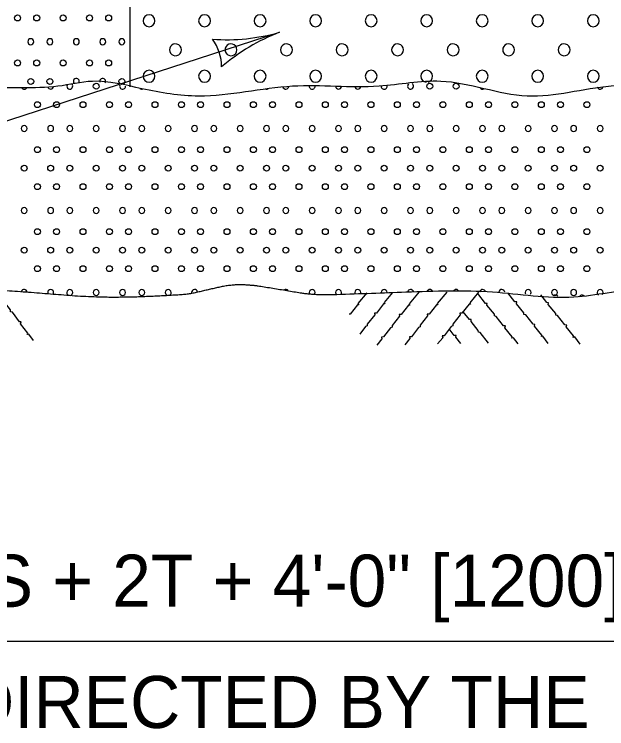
# Model space of a CAD drawing. Extents: x 49991.4 to 50021, y 49987.6 to 50011.4.
# Drawn here: x 50008.777 to 50009.461, y 49992.407 to 49993.231 of the extents above; entities that cross this region are included whole.
import ezdxf

# ---------------------------------------------------------------- set-up
doc = ezdxf.new("R2010")
doc.units = 0
for name, color, linetype in [('Level 1', 7, 'Continuous'), ('Level 2', 7, 'Continuous'), ('Level 3', 7, 'Continuous')]:
    doc.layers.add(name, color=color, linetype=linetype)

msp = doc.modelspace()

# ---------------------------------------------------------------- linework, layer by layer
at = {"layer": 'Level 1'}
msp.add_line((50008.91072, 49993.26941), (50008.91072, 49993.14749), dxfattribs=at)
for points in [[(50008.79939, 49992.85485), (50008.79419, 49992.86215), (50008.79239, 49992.86185), (50008.79279, 49992.86335), (50008.78469, 49992.87415), (50008.78529, 49992.87625), (50008.78319, 49992.87645), (50008.77509, 49992.88755), (50008.77309, 49992.88805), (50008.77289, 49992.89005), (50008.76479, 49992.90065), (50008.76519, 49992.90265), (50008.76309, 49992.90275), (50008.75679, 49992.91145)], [(50009.18429, 49992.90965), (50009.17409, 49992.89745), (50009.17499, 49992.89585), (50009.17339, 49992.89585), (50009.16499, 49992.88525), (50009.16389, 49992.88525)], [(50009.21399, 49992.91025), (50009.20439, 49992.89865), (50009.20519, 49992.89705), (50009.20359, 49992.89705), (50009.19529, 49992.88645), (50009.19309, 49992.88645), (50009.19339, 49992.88435), (50009.18479, 49992.87365), (50009.18479, 49992.87165), (50009.18289, 49992.87095), (50009.17609, 49992.86215)], [(50009.24469, 49992.91095), (50009.23309, 49992.89715), (50009.23389, 49992.89555), (50009.23229, 49992.89555), (50009.22399, 49992.88495), (50009.22179, 49992.88495), (50009.22209, 49992.88295), (50009.21349, 49992.87215), (50009.21349, 49992.87015), (50009.21169, 49992.86945), (50009.20349, 49992.85885), (50009.20139, 49992.85875), (50009.20179, 49992.85675), (50009.19589, 49992.84945)], [(50009.27649, 49992.91075), (50009.26539, 49992.89745), (50009.26619, 49992.89585), (50009.26459, 49992.89585), (50009.25619, 49992.88525), (50009.25409, 49992.88525), (50009.25439, 49992.88315), (50009.24569, 49992.87245), (50009.24569, 49992.87045), (50009.24389, 49992.86975), (50009.23569, 49992.85915), (50009.23369, 49992.85895), (50009.23409, 49992.85695), (50009.22809, 49992.84975)], [(50009.31329, 49992.91065), (50009.30309, 49992.89845), (50009.30389, 49992.89685), (50009.30229, 49992.89685), (50009.29399, 49992.88625), (50009.29179, 49992.88625), (50009.29209, 49992.88425), (50009.28349, 49992.87355), (50009.28349, 49992.87155), (50009.28169, 49992.87085), (50009.27349, 49992.86025), (50009.27139, 49992.86005), (50009.27189, 49992.85805), (50009.26589, 49992.85085)], [(50009.35899, 49992.85085), (50009.35359, 49992.85795), (50009.35179, 49992.85755), (50009.35219, 49992.85905), (50009.34379, 49992.86955), (50009.34419, 49992.87165), (50009.34219, 49992.87185), (50009.33369, 49992.88265), (50009.33169, 49992.88315), (50009.33149, 49992.88515), (50009.32299, 49992.89555), (50009.32329, 49992.89745), (50009.32129, 49992.89755), (50009.31249, 49992.90885)], [(50009.39379, 49992.85145), (50009.38749, 49992.85965), (50009.38579, 49992.85925), (50009.38619, 49992.86085), (50009.37769, 49992.87135), (50009.37819, 49992.87345), (50009.37619, 49992.87365), (50009.36769, 49992.88445), (50009.36569, 49992.88485), (50009.36549, 49992.88685), (50009.35699, 49992.89725), (50009.35729, 49992.89925), (50009.35519, 49992.89925), (50009.34699, 49992.90995)], [(50009.43059, 49992.85065), (50009.42439, 49992.85885), (50009.42259, 49992.85845), (50009.42299, 49992.86005), (50009.41459, 49992.87055), (50009.41509, 49992.87265), (50009.41299, 49992.87285), (50009.40449, 49992.88365), (50009.40259, 49992.88405), (50009.40229, 49992.88605), (50009.39379, 49992.89645), (50009.39419, 49992.89845), (50009.39209, 49992.89855), (50009.38499, 49992.90755)], [(50009.32489, 49992.85175), (50009.31519, 49992.86405), (50009.31329, 49992.86445), (50009.31299, 49992.86645), (50009.30459, 49992.87685), (50009.30489, 49992.87885), (50009.30279, 49992.87885), (50009.29569, 49992.88805)], [(50009.29299, 49992.85125), (50009.28699, 49992.85865), (50009.28729, 49992.86075), (50009.28519, 49992.86075), (50009.27939, 49992.86825)]]:
    msp.add_lwpolyline(points, dxfattribs=at)
for centre in [(50008.78109, 49993.22697), (50008.80323, 49993.22697), (50008.83371, 49993.22697), (50008.86419, 49993.22697), (50008.88633, 49993.22697), (50008.78109, 49993.17505), (50008.80323, 49993.17505), (50008.83371, 49993.17505), (50008.86419, 49993.17505), (50008.88633, 49993.17505), (50008.79633, 49993.15371), (50008.81847, 49993.15371), (50008.90157, 49993.15371), (50008.8719, 49993.14823), (50008.8719, 49993.14823), (50009.25692, 49993.14823), (50009.2874, 49993.14823), (50009.2874, 49993.14823), (50008.80404, 49993.1269), (50008.82618, 49993.1269), (50008.85666, 49993.1269), (50008.88714, 49993.1269), (50008.90928, 49993.1269), (50008.93976, 49993.1269), (50008.97024, 49993.1269), (50008.99238, 49993.1269), (50009.02286, 49993.1269), (50009.05334, 49993.1269), (50009.07548, 49993.1269), (50009.10596, 49993.1269), (50009.13644, 49993.1269), (50009.15858, 49993.1269), (50009.18906, 49993.1269), (50009.21954, 49993.1269), (50009.24168, 49993.1269), (50009.27216, 49993.1269), (50009.30264, 49993.1269), (50009.32478, 49993.1269), (50009.35526, 49993.1269), (50009.38574, 49993.1269), (50009.40788, 49993.1269), (50009.43836, 49993.1269), (50008.80404, 49993.07497), (50008.82618, 49993.07497), (50008.85666, 49993.07497), (50008.88714, 49993.07497), (50008.90928, 49993.07497), (50008.93976, 49993.07497), (50008.97024, 49993.07497), (50008.99238, 49993.07497), (50009.02286, 49993.07497), (50009.05334, 49993.07497), (50009.07548, 49993.07497), (50009.10596, 49993.07497), (50009.13644, 49993.07497), (50009.15858, 49993.07497), (50009.18906, 49993.07497), (50009.21954, 49993.07497), (50009.24168, 49993.07497), (50009.27216, 49993.07497), (50009.30264, 49993.07497), (50009.32478, 49993.07497), (50009.35526, 49993.07497), (50009.38574, 49993.07497), (50009.40788, 49993.07497), (50009.43836, 49993.07497), (50008.7888, 49993.05363), (50008.7888, 49993.05363), (50008.81928, 49993.05363), (50008.84142, 49993.05363), (50008.8719, 49993.05363), (50008.8719, 49993.05363), (50008.90238, 49993.05363), (50008.92452, 49993.05363), (50008.955, 49993.05363), (50008.955, 49993.05363), (50008.98548, 49993.05363), (50009.00762, 49993.05363), (50009.0381, 49993.05363), (50009.0381, 49993.05363), (50009.06858, 49993.05363), (50009.09072, 49993.05363), (50009.1212, 49993.05363), (50009.1212, 49993.05363), (50009.15168, 49993.05363), (50009.17382, 49993.05363), (50009.2043, 49993.05363), (50009.2043, 49993.05363), (50009.23478, 49993.05363), (50009.25692, 49993.05363), (50009.2874, 49993.05363), (50009.2874, 49993.05363), (50009.31788, 49993.05363), (50009.34002, 49993.05363), (50009.3705, 49993.05363), (50009.3705, 49993.05363), (50009.40098, 49993.05363), (50009.42312, 49993.05363), (50009.4536, 49993.05363), (50009.4536, 49993.05363), (50008.80404, 49993.0323), (50008.82618, 49993.0323), (50008.85666, 49993.0323), (50008.88714, 49993.0323), (50008.90928, 49993.0323), (50008.93976, 49993.0323), (50008.97024, 49993.0323), (50008.99238, 49993.0323), (50009.02286, 49993.0323), (50009.05334, 49993.0323), (50009.07548, 49993.0323), (50009.10596, 49993.0323), (50009.13644, 49993.0323), (50009.15858, 49993.0323), (50009.18906, 49993.0323), (50009.21954, 49993.0323), (50009.24168, 49993.0323), (50009.27216, 49993.0323), (50009.30264, 49993.0323), (50009.32478, 49993.0323), (50009.35526, 49993.0323), (50009.38574, 49993.0323), (50009.40788, 49993.0323), (50009.43836, 49993.0323), (50008.80404, 49992.98037), (50008.82618, 49992.98037), (50008.85666, 49992.98037), (50008.88714, 49992.98037), (50008.90928, 49992.98037), (50008.93976, 49992.98037), (50008.97024, 49992.98037), (50008.99238, 49992.98037), (50009.02286, 49992.98037), (50009.05334, 49992.98037), (50009.07548, 49992.98037), (50009.10596, 49992.98037), (50009.13644, 49992.98037), (50009.15858, 49992.98037), (50009.18906, 49992.98037), (50009.21954, 49992.98037), (50009.24168, 49992.98037), (50009.27216, 49992.98037), (50009.30264, 49992.98037), (50009.32478, 49992.98037), (50009.35526, 49992.98037), (50009.38574, 49992.98037), (50009.40788, 49992.98037), (50009.43836, 49992.98037), (50008.7888, 49992.95903), (50008.7888, 49992.95903), (50008.81928, 49992.95903), (50008.84142, 49992.95903), (50008.8719, 49992.95903), (50008.8719, 49992.95903), (50008.90238, 49992.95903), (50008.92452, 49992.95903), (50008.955, 49992.95903), (50008.955, 49992.95903), (50008.98548, 49992.95903), (50009.00762, 49992.95903), (50009.0381, 49992.95903), (50009.0381, 49992.95903), (50009.06858, 49992.95903), (50009.09072, 49992.95903), (50009.1212, 49992.95903), (50009.1212, 49992.95903), (50009.15168, 49992.95903), (50009.17382, 49992.95903), (50009.2043, 49992.95903), (50009.2043, 49992.95903), (50009.23478, 49992.95903), (50009.25692, 49992.95903), (50009.2874, 49992.95903), (50009.2874, 49992.95903), (50009.31788, 49992.95903), (50009.34002, 49992.95903), (50009.3705, 49992.95903), (50009.3705, 49992.95903), (50009.40098, 49992.95903), (50009.42312, 49992.95903), (50009.4536, 49992.95903), (50009.4536, 49992.95903), (50008.80404, 49992.9377), (50008.82618, 49992.9377), (50008.85666, 49992.9377), (50008.88714, 49992.9377), (50008.90928, 49992.9377), (50008.93976, 49992.9377), (50008.97024, 49992.9377), (50008.99238, 49992.9377), (50009.02286, 49992.9377), (50009.05334, 49992.9377), (50009.07548, 49992.9377), (50009.10596, 49992.9377), (50009.13644, 49992.9377), (50009.15858, 49992.9377), (50009.18906, 49992.9377), (50009.21954, 49992.9377), (50009.24168, 49992.9377), (50009.27216, 49992.9377), (50009.30264, 49992.9377), (50009.32478, 49992.9377), (50009.35526, 49992.9377), (50009.38574, 49992.9377), (50009.40788, 49992.9377), (50009.43836, 49992.9377)]:
    msp.add_circle(centre, 0.00341, dxfattribs=at)
for centre, radius, start, end in [((50008.93289, 49993.22381), 0.00682, 0, 180), ((50008.99699, 49993.22381), 0.00682, 0, 180), ((50009.06109, 49993.22381), 0.00682, 0, 180), ((50009.12519, 49993.22381), 0.00682, 0, 180), ((50009.18929, 49993.22381), 0.00682, 0, 180), ((50009.25339, 49993.22381), 0.00682, 0, 180), ((50009.31749, 49993.22381), 0.00682, 0, 180), ((50009.38159, 49993.22381), 0.00682, 0, 180), ((50009.44569, 49993.22381), 0.00682, 0, 180), ((50008.93289, 49993.22372), 0.00682, 180, 0), ((50008.99699, 49993.22372), 0.00682, 180, 0), ((50009.06109, 49993.22372), 0.00682, 180, 0), ((50009.12519, 49993.22372), 0.00682, 180, 0), ((50009.18929, 49993.22372), 0.00682, 180, 0), ((50009.25339, 49993.22372), 0.00682, 180, 0), ((50009.31749, 49993.22372), 0.00682, 180, 0), ((50009.38159, 49993.22372), 0.00682, 180, 0), ((50009.44569, 49993.22372), 0.00682, 180, 0), ((50008.79633, 49993.19954), 0.00341, 0, 180), ((50008.81847, 49993.19954), 0.00341, 0, 180), ((50008.84895, 49993.19954), 0.00341, 0, 180), ((50008.87943, 49993.19954), 0.00341, 0, 180), ((50008.90157, 49993.19954), 0.00341, 0, 180), ((50008.79633, 49993.19943), 0.00341, 180, 0), ((50008.81847, 49993.19943), 0.00341, 180, 0), ((50008.84895, 49993.19943), 0.00341, 180, 0), ((50008.84895, 49993.19943), 0.00341, 180, 0), ((50008.87943, 49993.19943), 0.00341, 180, 0), ((50008.90157, 49993.19943), 0.00341, 180, 0), ((50008.96337, 49993.19019), 0.00682, 77.07903, 282.92097), ((50008.96346, 49993.19019), 0.00682, 282.92097, 77.07903), ((50009.02747, 49993.19019), 0.00682, 77.07903, 282.92097), ((50009.02756, 49993.19019), 0.00682, 282.92097, 77.07903), ((50009.09157, 49993.19019), 0.00682, 77.07903, 282.92097), ((50009.09166, 49993.19019), 0.00682, 282.92097, 77.07903), ((50009.15567, 49993.19019), 0.00682, 77.07903, 282.92097), ((50009.15576, 49993.19019), 0.00682, 282.92097, 77.07903), ((50009.21977, 49993.19019), 0.00682, 77.07903, 282.92097), ((50009.21986, 49993.19019), 0.00682, 282.92097, 77.07903), ((50009.28387, 49993.19019), 0.00682, 77.07903, 282.92097), ((50009.28396, 49993.19019), 0.00682, 282.92097, 77.07903), ((50009.34797, 49993.19019), 0.00682, 77.07903, 282.92097), ((50009.34806, 49993.19019), 0.00682, 282.92097, 77.07903), ((50009.41207, 49993.19019), 0.00682, 77.07903, 282.92097), ((50009.41216, 49993.19019), 0.00682, 282.92097, 77.07903), ((50008.93289, 49993.15971), 0.00682, 0, 180), ((50008.99699, 49993.15971), 0.00682, 0, 180), ((50009.06109, 49993.15971), 0.00682, 0, 180), ((50009.12519, 49993.15971), 0.00682, 0, 180), ((50009.18929, 49993.15971), 0.00682, 0, 180), ((50009.25339, 49993.15971), 0.00682, 0, 180), ((50009.31749, 49993.15971), 0.00682, 0, 180), ((50009.38159, 49993.15971), 0.00682, 0, 180), ((50009.44569, 49993.15971), 0.00682, 0, 180), ((50008.84895, 49993.15371), 0.00341, 342.61051, 222.9149), ((50008.84895, 49993.15371), 0.00341, 342.61051, 222.9149), ((50008.87943, 49993.15371), 0.00341, 328.9106, 195.53658), ((50008.93289, 49993.15962), 0.00682, 180, 0), ((50008.99699, 49993.15962), 0.00682, 180, 0), ((50009.06109, 49993.15962), 0.00682, 180, 0), ((50009.12519, 49993.15962), 0.00682, 180, 0), ((50009.18929, 49993.15962), 0.00682, 180, 0), ((50009.25339, 49993.15962), 0.00682, 180, 265.65276), ((50009.25339, 49993.15962), 0.00682, 284.20444, 0), ((50009.31749, 49993.15962), 0.00682, 180, 0), ((50009.38159, 49993.15962), 0.00682, 180, 0), ((50009.44569, 49993.15962), 0.00682, 180, 0), ((50008.7888, 49993.14823), 0.00341, 212.56079, 331.97835), ((50008.7888, 49993.14823), 0.00341, 212.56079, 331.97835), ((50008.81928, 49993.14823), 0.00341, 190.41263, 354.26617), ((50008.84142, 49993.14823), 0.00341, 157.68095, 47.56329), ((50008.90238, 49993.14823), 0.00341, 161.68622, 359.47021), ((50008.92452, 49993.14823), 0.00341, 230.05772, 294.18386), ((50009.06858, 49993.14823), 0.00341, 257.49086, 299.73404), ((50009.09072, 49993.14823), 0.00341, 193.42137, 355.72087), ((50009.1212, 49993.14823), 0.00341, 177.78109, 2.07088), ((50009.1212, 49993.14823), 0.00341, 177.78109, 2.07088), ((50009.15168, 49993.14823), 0.00341, 181.6299, 356.93011), ((50009.17382, 49993.14823), 0.00341, 185.5721, 353.98499), ((50009.2043, 49993.14823), 0.00341, 181.2861, 3.79327), ((50009.2043, 49993.14823), 0.00341, 181.2861, 3.79327), ((50009.23478, 49993.14823), 0.00341, 131.95947, 60.34325), ((50009.31788, 49993.14823), 0.00341, 209.9876, 299.87473), ((50009.4536, 49993.14823), 0.00341, 198.22685, 351.0242), ((50009.4536, 49993.14823), 0.00341, 198.22685, 351.0242), ((50008.7888, 49993.09946), 0.00341, 0, 180), ((50008.7888, 49993.09935), 0.00341, 180, 0), ((50008.7888, 49993.09935), 0.00341, 180, 0), ((50008.81928, 49993.09946), 0.00341, 0, 180), ((50008.81928, 49993.09935), 0.00341, 180, 0), ((50008.84142, 49993.09946), 0.00341, 0, 180), ((50008.84142, 49993.09935), 0.00341, 180, 0), ((50008.8719, 49993.09946), 0.00341, 0, 180), ((50008.8719, 49993.09935), 0.00341, 180, 0), ((50008.8719, 49993.09935), 0.00341, 180, 0), ((50008.90238, 49993.09946), 0.00341, 0, 180), ((50008.90238, 49993.09935), 0.00341, 180, 0), ((50008.92452, 49993.09946), 0.00341, 0, 180), ((50008.92452, 49993.09935), 0.00341, 180, 0), ((50008.955, 49993.09946), 0.00341, 0, 180), ((50008.955, 49993.09935), 0.00341, 180, 0), ((50008.955, 49993.09935), 0.00341, 180, 0), ((50008.98548, 49993.09946), 0.00341, 0, 180), ((50008.98548, 49993.09935), 0.00341, 180, 0), ((50009.00762, 49993.09946), 0.00341, 0, 180), ((50009.00762, 49993.09935), 0.00341, 180, 0), ((50009.0381, 49993.09946), 0.00341, 0, 180), ((50009.0381, 49993.09935), 0.00341, 180, 0), ((50009.0381, 49993.09935), 0.00341, 180, 0), ((50009.06858, 49993.09946), 0.00341, 0, 180), ((50009.06858, 49993.09935), 0.00341, 180, 0), ((50009.09072, 49993.09946), 0.00341, 0, 180), ((50009.09072, 49993.09935), 0.00341, 180, 0), ((50009.1212, 49993.09946), 0.00341, 0, 180), ((50009.1212, 49993.09935), 0.00341, 180, 0), ((50009.1212, 49993.09935), 0.00341, 180, 0), ((50009.15168, 49993.09946), 0.00341, 0, 180), ((50009.15168, 49993.09935), 0.00341, 180, 0), ((50009.17382, 49993.09946), 0.00341, 0, 180), ((50009.17382, 49993.09935), 0.00341, 180, 0), ((50009.2043, 49993.09946), 0.00341, 0, 180), ((50009.2043, 49993.09935), 0.00341, 180, 0), ((50009.2043, 49993.09935), 0.00341, 180, 0), ((50009.23478, 49993.09946), 0.00341, 0, 180), ((50009.23478, 49993.09935), 0.00341, 180, 0), ((50009.25692, 49993.09946), 0.00341, 0, 180), ((50009.25692, 49993.09935), 0.00341, 180, 0), ((50009.2874, 49993.09946), 0.00341, 0, 180), ((50009.2874, 49993.09935), 0.00341, 180, 0), ((50009.2874, 49993.09935), 0.00341, 180, 0), ((50009.31788, 49993.09946), 0.00341, 0, 180), ((50009.31788, 49993.09935), 0.00341, 180, 0), ((50009.34002, 49993.09946), 0.00341, 0, 180), ((50009.34002, 49993.09935), 0.00341, 180, 0), ((50009.3705, 49993.09946), 0.00341, 0, 180), ((50009.3705, 49993.09935), 0.00341, 180, 0), ((50009.3705, 49993.09935), 0.00341, 180, 0), ((50009.40098, 49993.09946), 0.00341, 0, 180), ((50009.40098, 49993.09935), 0.00341, 180, 0), ((50009.42312, 49993.09946), 0.00341, 0, 180), ((50009.42312, 49993.09935), 0.00341, 180, 0), ((50009.4536, 49993.09946), 0.00341, 0, 180), ((50009.4536, 49993.09935), 0.00341, 180, 0), ((50009.4536, 49993.09935), 0.00341, 180, 0), ((50008.7888, 49993.00486), 0.00341, 0, 180), ((50008.7888, 49993.00475), 0.00341, 180, 0), ((50008.7888, 49993.00475), 0.00341, 180, 0), ((50008.81928, 49993.00486), 0.00341, 0, 180), ((50008.81928, 49993.00475), 0.00341, 180, 0), ((50008.84142, 49993.00486), 0.00341, 0, 180), ((50008.84142, 49993.00475), 0.00341, 180, 0), ((50008.8719, 49993.00486), 0.00341, 0, 180), ((50008.8719, 49993.00475), 0.00341, 180, 0), ((50008.8719, 49993.00475), 0.00341, 180, 0), ((50008.90238, 49993.00486), 0.00341, 0, 180), ((50008.90238, 49993.00475), 0.00341, 180, 0), ((50008.92452, 49993.00486), 0.00341, 0, 180), ((50008.92452, 49993.00475), 0.00341, 180, 0), ((50008.955, 49993.00486), 0.00341, 0, 180), ((50008.955, 49993.00475), 0.00341, 180, 0), ((50008.955, 49993.00475), 0.00341, 180, 0), ((50008.98548, 49993.00486), 0.00341, 0, 180), ((50008.98548, 49993.00475), 0.00341, 180, 0), ((50009.00762, 49993.00486), 0.00341, 0, 180), ((50009.00762, 49993.00475), 0.00341, 180, 0), ((50009.0381, 49993.00486), 0.00341, 0, 180), ((50009.0381, 49993.00475), 0.00341, 180, 0), ((50009.0381, 49993.00475), 0.00341, 180, 0), ((50009.06858, 49993.00486), 0.00341, 0, 180), ((50009.06858, 49993.00475), 0.00341, 180, 0), ((50009.09072, 49993.00486), 0.00341, 0, 180), ((50009.09072, 49993.00475), 0.00341, 180, 0), ((50009.1212, 49993.00486), 0.00341, 0, 180), ((50009.1212, 49993.00475), 0.00341, 180, 0), ((50009.1212, 49993.00475), 0.00341, 180, 0), ((50009.15168, 49993.00486), 0.00341, 0, 180), ((50009.15168, 49993.00475), 0.00341, 180, 0), ((50009.17382, 49993.00486), 0.00341, 0, 180), ((50009.17382, 49993.00475), 0.00341, 180, 0), ((50009.2043, 49993.00486), 0.00341, 0, 180), ((50009.2043, 49993.00475), 0.00341, 180, 0), ((50009.2043, 49993.00475), 0.00341, 180, 0), ((50009.23478, 49993.00486), 0.00341, 0, 180), ((50009.23478, 49993.00475), 0.00341, 180, 0), ((50009.25692, 49993.00486), 0.00341, 0, 180), ((50009.25692, 49993.00475), 0.00341, 180, 0), ((50009.2874, 49993.00486), 0.00341, 0, 180), ((50009.2874, 49993.00475), 0.00341, 180, 0), ((50009.2874, 49993.00475), 0.00341, 180, 0), ((50009.31788, 49993.00486), 0.00341, 0, 180), ((50009.31788, 49993.00475), 0.00341, 180, 0), ((50009.34002, 49993.00486), 0.00341, 0, 180), ((50009.34002, 49993.00475), 0.00341, 180, 0), ((50009.3705, 49993.00486), 0.00341, 0, 180), ((50009.3705, 49993.00475), 0.00341, 180, 0), ((50009.3705, 49993.00475), 0.00341, 180, 0), ((50009.40098, 49993.00486), 0.00341, 0, 180), ((50009.40098, 49993.00475), 0.00341, 180, 0), ((50009.42312, 49993.00486), 0.00341, 0, 180), ((50009.42312, 49993.00475), 0.00341, 180, 0), ((50009.4536, 49993.00486), 0.00341, 0, 180), ((50009.4536, 49993.00475), 0.00341, 180, 0), ((50009.4536, 49993.00475), 0.00341, 180, 0), ((50008.7888, 49992.91026), 0.00341, 9.36974, 162.18249), ((50008.81928, 49992.91026), 0.00341, 0, 180), ((50008.81928, 49992.91015), 0.00341, 180, 201.78419), ((50008.81928, 49992.91015), 0.00341, 329.118, 0), ((50008.84142, 49992.91026), 0.00341, 0, 180), ((50008.84142, 49992.91015), 0.00341, 180, 245.20508), ((50008.84142, 49992.91015), 0.00341, 286.84555, 0), ((50008.8719, 49992.91026), 0.00341, 0, 180), ((50008.8719, 49992.91015), 0.00341, 180, 0), ((50008.8719, 49992.91015), 0.00341, 180, 0), ((50008.90238, 49992.91026), 0.00341, 0, 180), ((50008.90238, 49992.91015), 0.00341, 180, 0), ((50008.92452, 49992.91026), 0.00341, 0, 180), ((50008.92452, 49992.91015), 0.00341, 180, 0), ((50008.955, 49992.91026), 0.00341, 0, 180), ((50008.955, 49992.91015), 0.00341, 180, 249.35716), ((50008.955, 49992.91015), 0.00341, 180, 249.35716), ((50008.955, 49992.91015), 0.00341, 297.32148, 0), ((50008.955, 49992.91015), 0.00341, 297.32148, 0), ((50008.98548, 49992.91026), 0.00341, 8.29256, 180), ((50008.98548, 49992.91015), 0.00341, 180, 192.8085), ((50009.09072, 49992.91026), 0.00341, 32.27072, 127.6124), ((50009.1212, 49992.91026), 0.00341, 0, 180), ((50009.1212, 49992.91015), 0.00341, 180, 206.62838), ((50009.1212, 49992.91015), 0.00341, 180, 206.62838), ((50009.1212, 49992.91015), 0.00341, 324.25648, 0), ((50009.1212, 49992.91015), 0.00341, 324.25648, 0), ((50009.15168, 49992.91026), 0.00341, 0, 180), ((50009.15168, 49992.91015), 0.00341, 180, 220.36692), ((50009.15168, 49992.91015), 0.00341, 323.29209, 0), ((50009.17382, 49992.91026), 0.00341, 0, 180), ((50009.17382, 49992.91015), 0.00341, 180, 205.1794), ((50009.17382, 49992.91015), 0.00341, 338.99527, 0), ((50009.2043, 49992.91026), 0.00341, 0, 180), ((50009.2043, 49992.91015), 0.00341, 180, 185.78551), ((50009.2043, 49992.91015), 0.00341, 180, 185.78551), ((50009.2043, 49992.91015), 0.00341, 358.41335, 0), ((50009.2043, 49992.91015), 0.00341, 358.41335, 0), ((50009.23478, 49992.91026), 0.00341, 14.46685, 168.99866), ((50009.25692, 49992.91026), 0.00341, 20.23317, 160.76844), ((50009.2874, 49992.91026), 0.00341, 18.1476, 160.71787), ((50009.31788, 49992.91026), 0.00341, 11.39988, 167.10892), ((50009.34002, 49992.91026), 0.00341, 2.80769, 172.54362), ((50009.3705, 49992.91026), 0.00341, 0, 180), ((50009.3705, 49992.91015), 0.00341, 180, 202.62202), ((50009.3705, 49992.91015), 0.00341, 180, 202.62202), ((50009.3705, 49992.91015), 0.00341, 328.00898, 0), ((50009.3705, 49992.91015), 0.00341, 328.00898, 0), ((50009.40098, 49992.91026), 0.00341, 0, 180), ((50009.40098, 49992.91015), 0.00341, 180, 0), ((50009.40223, 49992.90376), 0.00341, 39.1643, 133.18809), ((50009.40223, 49992.90376), 0.00341, 39.1643, 133.18809), ((50009.42312, 49992.91026), 0.00341, 0, 180), ((50009.42312, 49992.91015), 0.00341, 180, 0), ((50009.43271, 49992.90376), 0.00341, 30.42254, 155.89053), ((50009.4536, 49992.91026), 0.00341, 0, 180), ((50009.4536, 49992.91015), 0.00341, 180, 235.47793), ((50009.4536, 49992.91015), 0.00341, 180, 235.47793), ((50009.4536, 49992.91015), 0.00341, 321.59835, 0), ((50009.4536, 49992.91015), 0.00341, 321.59835, 0)]:
    msp.add_arc(centre, radius, start, end, dxfattribs=at)
for points in [[(50009.63137, 49993.1424), (50009.62317, 49993.1424), (50009.51477, 49993.1481), (50009.46637, 49993.1481), (50009.36937, 49993.1368), (50009.26957, 49993.1538), (50009.19837, 49993.1481), (50009.09857, 49993.1481), (50008.99017, 49993.1368), (50008.92467, 49993.1453), (50008.86757, 49993.1538), (50008.82767, 49993.1481), (50008.78607, 49993.1464)], [(50008.78607, 49993.1464), (50008.66427, 49993.1481), (50008.59057, 49993.1505), (50008.51697, 49993.1458), (50008.42407, 49993.1463)], [(50009.14959, 49992.90795), (50009.22949, 49992.91085), (50009.32929, 49992.91085), (50009.42329, 49992.90515), (50009.50029, 49992.91365), (50009.60299, 49992.90515), (50009.65999, 49992.91365), (50009.74269, 49992.91085), (50009.79491, 49992.91051)]]:
    msp.add_spline(points, degree=3, dxfattribs=at)
msp.add_open_spline([(50008.69405, 49992.91247), (50008.70526, 49992.91324), (50008.71647, 49992.91359), (50008.72769, 49992.91365), (50008.74028, 49992.91371), (50008.75288, 49992.91345), (50008.76547, 49992.91261), (50008.77808, 49992.91178), (50008.79065, 49992.91088), (50008.80324, 49992.90994), (50008.81583, 49992.90899), (50008.82841, 49992.90792), (50008.84101, 49992.90699), (50008.85359, 49992.90606), (50008.86618, 49992.90548), (50008.87879, 49992.90515), (50008.88638, 49992.90494), (50008.89398, 49992.90492), (50008.90158, 49992.90503), (50008.90919, 49992.90514), (50008.91679, 49992.90528), (50008.92439, 49992.90557), (50008.932, 49992.90586), (50008.9396, 49992.90624), (50008.9472, 49992.9066), (50008.9548, 49992.90697), (50008.96239, 49992.90741), (50008.96999, 49992.90795), (50008.97553, 49992.90834), (50008.98105, 49992.90908), (50008.98649, 49992.91028), (50008.99196, 49992.91148), (50008.99739, 49992.91283), (50009.00285, 49992.91406), (50009.00828, 49992.91528), (50009.01372, 49992.91649), (50009.01918, 49992.91763), (50009.02188, 49992.9182), (50009.02461, 49992.91852), (50009.02736, 49992.91882), (50009.0301, 49992.91913), (50009.03284, 49992.91931), (50009.03559, 49992.91935), (50009.03961, 49992.9194), (50009.04364, 49992.91928), (50009.04767, 49992.91899), (50009.05171, 49992.91869), (50009.05575, 49992.9184), (50009.05974, 49992.91776), (50009.06781, 49992.91646), (50009.07586, 49992.91514), (50009.08392, 49992.91382), (50009.092, 49992.91249), (50009.10007, 49992.91111), (50009.10816, 49992.90979), (50009.11218, 49992.90913), (50009.11624, 49992.90874), (50009.12031, 49992.90845), (50009.12436, 49992.90817), (50009.12842, 49992.90795), (50009.13249, 49992.90795), (50009.13819, 49992.90795), (50009.14389, 49992.90795), (50009.14959, 49992.90795)], degree=3, dxfattribs=at)
at = {"layer": 'Level 3'}
for p, q in [((50008.07804, 49992.88403), (50009.08365, 49993.21045)), ((50008.2551, 49992.50774), (50010.24289, 49992.50774))]:
    msp.add_line(p, q, dxfattribs=at)
for centre, radius, start, end in [((50009.02244, 49993.42417), 0.22232, 265.79822, 285.98173), ((50008.96195, 49993.1701), 0.05477, 0.48103, 36.20339), ((50009.16779, 49992.99317), 0.233, 111.16952, 130.41937)]:
    msp.add_arc(centre, radius, start, end, dxfattribs=at)

# ---------------------------------------------------------------- texts
at = {"layer": 'Level 2'}
for s, p in [('(S + 2T + 4\'-0" [1200])', (50008.71875, 49992.54774)), ('OR AS DIRECTED BY THE PROJECT', (50008.44732, 49992.40774))]:
    msp.add_text(s, height=0.06, dxfattribs=at).set_placement(p)

doc.saveas('drawing.dxf')
